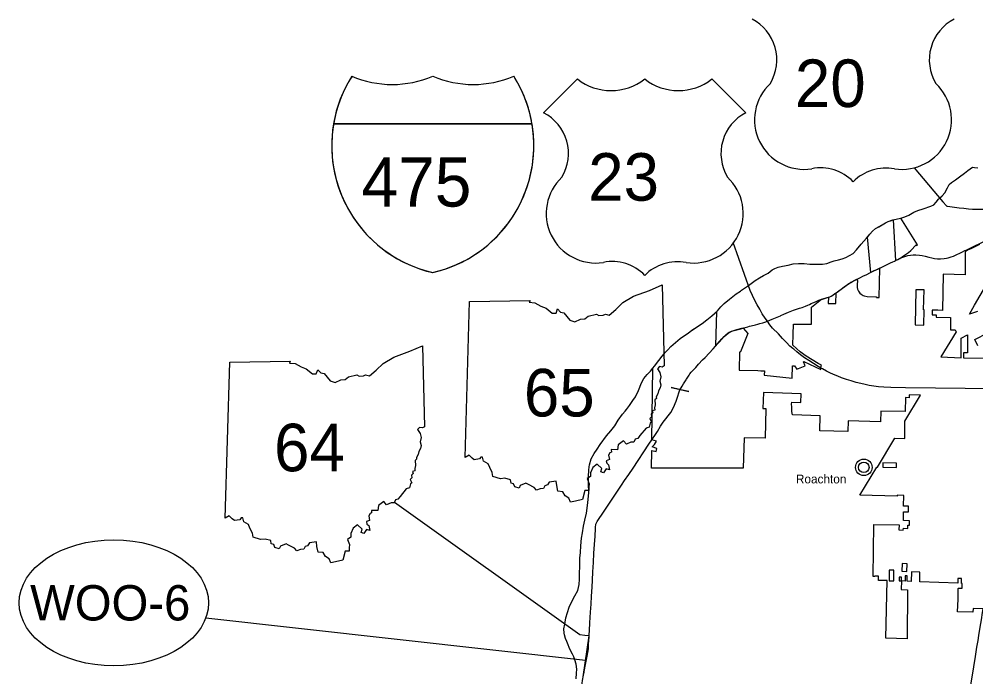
# Model space of a CAD drawing. Extents: x 0 to 851, y 0 to 440.
# Drawn here: x 242.7 to 318.5, y 285 to 337.1 of the extents above; entities that cross this region are included whole.
import ezdxf

# ---------------------------------------------------------------- set-up
doc = ezdxf.new("R2010")
doc.units = 0
for name, color, linetype in [('DV_X_Corp_Line', 7, 'Continuous'), ('GM_X_County', 7, 'Continuous'), ('GM_X_Interstate_Route', 7, 'Continuous'), ('GM_X_State_Route', 7, 'Continuous'), ('GM_X_US_Route', 7, 'Continuous'), ('PV_P_Text', 7, 'Continuous'), ('RD_P_Fence', 7, 'Continuous'), ('SH_Data', 7, 'Continuous')]:
    doc.layers.add(name, color=color, linetype=linetype)

msp = doc.modelspace()

# ---------------------------------------------------------------- linework, layer by layer
at = {"layer": 'DV_X_Corp_Line'}
for points in [[(319.048, 290.414), (318.275, 290.42), (318.257, 290.139), (317.045, 290.161), (317.103, 291.162), (317.111, 292.029), (317.12, 292.049), (317.141, 292.053), (317.415, 292.051), (317.428, 292.418), (317.352, 292.419), (317.357, 292.803), (317.08, 292.81), (317.081, 292.429), (314.051, 292.548), (314.062, 293.308), (313.41, 293.336), (313.376, 292.574), (313.052, 292.589), (313.057, 293.014), (312.902, 293.016), (312.893, 292.596), (312.616, 292.617), (312.592, 291.932), (313.091, 291.917), (313.053, 288.016), (311.365, 288.075), (311.466, 292.647), (310.784, 292.657), (310.797, 292.994), (310.489, 293.006), (310.488, 292.965), (310.356, 292.968), (310.419, 297.085), (312.425, 297.052), (312.413, 296.66), (312.753, 296.64), (312.758, 296.793), (313.108, 296.78), (313.119, 297.038), (313.254, 297.041), (313.257, 297.37), (312.767, 297.395), (312.766, 298.098), (313.154, 298.096), (313.158, 298.537), (312.773, 298.549), (312.795, 299.398), (312.256, 299.407), (312.256, 299.338), (309.321, 299.406), (310.645, 301.632), (310.716, 301.631), (312.076, 303.924), (312.866, 303.916), (312.872, 304.289), (312.887, 305.289), (314.122, 307.353), (313.218, 307.36), (313.209, 307.135), (312.92, 307.148), (312.9, 306.055), (310.973, 306.075), (310.955, 305.238), (308.39, 305.295), (308.367, 304.469), (306.152, 304.505), (306.17, 305.694), (303.972, 305.77), (303.938, 306.056), (303.919, 306.278), (303.915, 306.341), (303.913, 306.414), (303.912, 306.62), (303.913, 306.779), (304.637, 306.758), (304.665, 307.454), (303.929, 307.482), (301.677, 307.542), (301.64, 306.287), (301.875, 306.277), (301.825, 303.923), (300.143, 303.957), (300.078, 301.55), (297.691, 301.546), (297.634, 301.546), (295.605, 301.549), (292.807, 301.55), (292.841, 302.947), (293.173, 302.886), (293.23, 303.108), (292.874, 303.258), (293.057, 303.435), (293.217, 303.684), (292.846, 303.801), (292.924, 309.486), (293.045, 309.641), (293.382, 310.094), (293.657, 310.441), (293.918, 310.754), (294.105, 310.942), (294.345, 311.186), (294.711, 311.518), (295.083, 311.826), (295.421, 312.081), (295.704, 312.266), (295.863, 312.382), (296.44, 312.769), (296.547, 312.84), (296.828, 313.03), (297.207, 313.298), (297.599, 313.616), (297.951, 313.942), (297.893, 311.27), (298.192, 311.57), (298.394, 311.782), (298.576, 311.991), (298.728, 312.13), (298.879, 312.254), (298.985, 312.323), (299.07, 312.37), (299.142, 312.404), (299.254, 312.442), (299.561, 312.525), (299.77, 312.578), (300.073, 312.657), (300.432, 312.216), (299.849, 310.77), (299.794, 310.741), (299.75, 309.319), (301.234, 309.282), (301.475, 309.279), (301.751, 309.275), (301.736, 308.927), (303.958, 308.7), (303.982, 309.669), (304.057, 309.662), (304.129, 309.659), (304.313, 309.401), (304.973, 309.663), (304.853, 309.992), (304.88, 310.011), (306.217, 309.364), (306.234, 309.562), (306.269, 309.717), (306.011, 309.839), (305.074, 310.442), (304.598, 310.784), (304.012, 311.293), (304.033, 312.145), (304.049, 312.956), (305.489, 312.979), (305.489, 314.316), (306.285, 314.937), (306.469, 314.996), (306.581, 315.031), (306.837, 315.11), (306.809, 314.609), (307.418, 314.618), (307.445, 315.464), (307.51, 315.513), (307.827, 315.74), (308.108, 315.944), (308.222, 316.024), (308.449, 316.187), (308.515, 316.229), (308.605, 316.286), (308.688, 316.335), (308.731, 316.358), (308.814, 316.401), (308.923, 316.457), (309.062, 316.526), (309.08, 316.482), (309.089, 316.486), (309.131, 316.402), (309.096, 316.116), (309.102, 315.879), (309.127, 315.747), (309.206, 315.578), (309.318, 315.428), (309.428, 315.337), (309.574, 315.239), (309.644, 315.209), (309.893, 315.154), (310.585, 315.14), (310.632, 315.131), (310.639, 315.072), (310.855, 315.073), (310.886, 317.409), (310.569, 317.258), (310.431, 317.195), (310.183, 317.072), (309.931, 319.871), (310.107, 320.097), (310.308, 320.34), (310.558, 320.546), (310.824, 320.691), (311.35, 321.001), (311.546, 321.106), (311.815, 321.194), (311.916, 321.227), (311.942, 321.232), (312.141, 318.01), (312.491, 318.177), (312.841, 318.426), (313.156, 318.641), (313.353, 318.808), (313.764, 319.245), (313.799, 319.202), (313.882, 319.258), (312.571, 321.371), (312.883, 321.471), (313.193, 321.612), (313.577, 321.836), (313.897, 321.974), (314.317, 322.104), (314.926, 322.312), (315.165, 322.43), (315.355, 322.647), (315.546, 322.887), (315.826, 323.129), (316.047, 323.389), (316.246, 323.766), (316.376, 324.027), (316.579, 324.183), (316.9, 324.415), (317.214, 324.643), (317.595, 324.928), (317.863, 325.157), (318.227, 325.405), (318.398, 325.396), (318.649, 325.36)], [(318.793, 319.294), (318.462, 319.131), (318.146, 318.978), (317.846, 318.825), (317.644, 318.706), (317.642, 316.884), (315.916, 316.93), (315.868, 314.056), (315.494, 314.068), (315.048, 314.075), (315.036, 313.702), (315.35, 313.703), (315.358, 313.52), (316.492, 313.502), (316.492, 312.53), (316.857, 312.524), (316.931, 312.354), (315.734, 310.388), (317.333, 310.295), (317.332, 311.857), (317.831, 312.134), (317.831, 310.704), (317.515, 310.698), (317.515, 310.294), (320.058, 310.283)], [(318.637, 313.963), (318.007, 313.758), (318.396, 314.465), (320.198, 317.551)], [(318.668, 311.238), (318.431, 311.762), (319.452, 312.281)]]:
    msp.add_lwpolyline(points, dxfattribs=at)
for points in [[(313.698, 312.902), (314.378, 312.878), (314.405, 314.099), (314.353, 314.1), (314.406, 315.687), (313.733, 315.696)], [(295.077, 307.794), (295.037, 307.802), (294.381, 307.942)], [(295.766, 307.632), (295.135, 307.766), (295.086, 307.777)], [(312.22, 301.616), (312.223, 301.957), (311.133, 301.976), (311.13, 301.627)], [(312.663, 293.991), (312.642, 293.396), (313.034, 293.367), (313.056, 293.979)], [(311.632, 292.637), (312.016, 292.628), (312.016, 293.48), (311.632, 293.48)], [(312.616, 292.617), (312.615, 292.903), (312.419, 292.903), (312.415, 292.624)]]:
    msp.add_lwpolyline(points, close=True, dxfattribs=at)
for radius in [0.658, 0.417]:
    msp.add_circle((309.626, 301.62), radius, dxfattribs=at)
at = {"layer": 'GM_X_County'}
msp.add_lwpolyline([(286.857, 284.869), (286.885, 285.309), (286.901, 285.632), (286.84, 286.009), (286.748, 286.351), (286.652, 286.601), (286.548, 286.808), (286.385, 287.103), (286.288, 287.33), (286.208, 287.56), (286.098, 287.824), (286.005, 288.051), (285.912, 288.345), (285.897, 288.482), (285.861, 288.816), (285.949, 289.184), (286.039, 289.691), (286.148, 290.116), (286.293, 290.525), (286.533, 291.04), (286.736, 291.444), (286.975, 291.855), (287.091, 292.324), (287.103, 292.764), (287.118, 293.211), (287.138, 293.782), (287.148, 294.414), (287.197, 294.881), (287.217, 295.405), (287.257, 296.003), (287.336, 296.425), (287.425, 296.945), (287.538, 297.428), (287.659, 297.998), (287.752, 298.592), (287.788, 299.069), (287.838, 299.63), (287.816, 300.309), (287.829, 300.903), (287.838, 301.384), (287.873, 301.661), (287.893, 301.82), (288.029, 302.283), (288.282, 302.72), (288.504, 303.05), (288.759, 303.434), (289.256, 304.104), (289.579, 304.51), (289.902, 304.914), (290.172, 305.351), (290.526, 305.831), (290.716, 306.066), (290.838, 306.217), (291.073, 306.53), (291.339, 306.914), (291.54, 307.221), (291.783, 307.709), (292.025, 308.311), (292.203, 308.649), (292.471, 308.972), (292.742, 309.254), (292.924, 309.486), (293.045, 309.641), (293.382, 310.094), (293.657, 310.441), (293.918, 310.754), (294.105, 310.942), (294.345, 311.186), (294.711, 311.518), (295.083, 311.826), (295.421, 312.081), (295.704, 312.266), (295.863, 312.382), (296.083, 312.541), (296.44, 312.769), (296.828, 313.03), (297.207, 313.298), (297.599, 313.616), (298.029, 314.015), (298.304, 314.341), (298.558, 314.6), (298.988, 314.959), (299.512, 315.366), (299.854, 315.595), (299.947, 315.657), (300.497, 316.023), (301.031, 316.428), (301.375, 316.636), (301.685, 316.824), (302.039, 317.011), (302.364, 317.273), (302.58, 317.392), (302.855, 317.476), (303.191, 317.553), (303.628, 317.649), (304.028, 317.759), (304.453, 317.784), (304.909, 317.769), (305.36, 317.73), (305.836, 317.722), (306.342, 317.716), (306.687, 317.769), (307.041, 317.896), (307.289, 317.984), (307.629, 318.071), (307.921, 318.135), (308.197, 318.253), (308.787, 318.566), (309.051, 318.859), (309.415, 319.305), (309.852, 319.771), (310.107, 320.097), (310.308, 320.34), (310.558, 320.546), (310.902, 320.734), (311.35, 321.001), (311.546, 321.106), (311.916, 321.227), (312.571, 321.37), (312.883, 321.471), (313.193, 321.612), (313.577, 321.836), (313.897, 321.974), (314.317, 322.104), (314.926, 322.312), (315.165, 322.43), (315.355, 322.647), (315.546, 322.887), (315.631, 322.961), (315.826, 323.129), (316.047, 323.389), (316.246, 323.766), (316.376, 324.027), (316.579, 324.183), (316.9, 324.415), (317.214, 324.643), (317.595, 324.928), (317.863, 325.157), (318.227, 325.405), (318.398, 325.396), (318.649, 325.36)], dxfattribs=at)
at = {"layer": 'GM_X_Interstate_Route'}
for points in [[(301.992, 313.205), (301.816, 313.453), (301.587, 313.791), (301.383, 314.151), (301.184, 314.507), (300.973, 314.893), (300.804, 315.228), (300.639, 315.625), (299.276, 319.435)], [(306.144, 309.54), (306.135, 309.545), (306.02, 309.609), (305.629, 309.847), (305.262, 310.081), (304.937, 310.294), (304.617, 310.524), (304.319, 310.767), (304.072, 310.976), (304.002, 311.038), (303.778, 311.236), (303.505, 311.502), (303.199, 311.819), (302.857, 312.204), (302.396, 312.638), (302.179, 312.914), (301.992, 313.205)], [(321.825, 307.801), (320.133, 307.84), (320.02, 307.851), (312.929, 307.924), (311.76, 307.955), (311.222, 307.978), (310.795, 308.013), (310.42, 308.043), (310.05, 308.113), (309.736, 308.178), (309.383, 308.257), (309.023, 308.354), (308.624, 308.464), (308.248, 308.584), (307.869, 308.711), (307.566, 308.836), (307.238, 308.986), (306.945, 309.115), (306.66, 309.253), (306.342, 309.43), (306.144, 309.54)]]:
    msp.add_lwpolyline(points, dxfattribs=at)
at = {"layer": 'GM_X_State_Route'}
for points in [[(317.622, 318.794), (317.676, 318.819), (318.368, 319.149), (318.87, 319.384), (320.312, 320.085)], [(312.045, 317.966), (312.138, 318.008), (312.312, 318.088), (312.461, 318.166), (312.573, 318.213), (312.704, 318.273), (312.866, 318.332), (313.109, 318.402), (313.323, 318.442), (313.533, 318.457), (313.741, 318.47)], [(313.741, 318.47), (314.046, 318.441), (314.251, 318.404), (314.489, 318.355), (314.773, 318.285), (315.014, 318.23), (315.237, 318.184), (315.473, 318.154), (315.705, 318.151), (315.989, 318.169), (316.17, 318.199), (316.3, 318.224), (316.38, 318.245), (316.538, 318.297), (316.719, 318.364), (316.997, 318.49), (317.221, 318.593), (317.442, 318.708), (317.622, 318.794)], [(310.834, 317.39), (310.886, 317.414), (311.318, 317.615), (311.75, 317.822), (311.927, 317.912), (312.045, 317.966)], [(308.89, 316.438), (309.089, 316.54), (309.361, 316.674), (309.542, 316.761), (309.874, 316.917), (310.101, 317.035)], [(310.101, 317.035), (310.164, 317.068), (310.431, 317.195), (310.564, 317.258), (310.781, 317.366), (310.834, 317.39)], [(307.66, 315.611), (307.827, 315.73), (308.125, 315.956), (308.236, 316.041), (308.463, 316.197), (308.584, 316.269)], [(308.584, 316.269), (308.589, 316.272), (308.734, 316.359), (308.89, 316.438)], [(306.929, 315.138), (306.94, 315.142), (307.048, 315.193), (307.184, 315.275), (307.337, 315.386), (307.446, 315.46)], [(307.446, 315.46), (307.546, 315.529), (307.66, 315.611)], [(304.066, 314.086), (304.066, 314.086), (304.212, 314.128), (304.545, 314.229), (304.745, 314.293), (304.866, 314.332), (305.011, 314.39), (305.199, 314.478), (305.331, 314.536), (305.445, 314.601), (305.577, 314.66), (305.812, 314.747), (306.065, 314.862), (306.231, 314.921), (306.332, 314.954), (306.345, 314.957)], [(306.345, 314.957), (306.73, 315.073), (306.929, 315.138)], [(303.033, 313.637), (303.06, 313.649), (303.286, 313.748), (303.66, 313.911), (304.066, 314.086)], [(300.449, 312.769), (300.566, 312.8), (300.71, 312.838), (301.046, 312.92), (301.231, 312.965), (301.385, 313.013), (301.618, 313.071), (301.797, 313.134), (301.992, 313.205)], [(301.992, 313.205), (302.373, 313.355), (302.764, 313.518), (303.033, 313.637)], [(297.702, 311.025), (297.88, 311.213), (298.19, 311.591), (298.377, 311.793), (298.568, 311.999), (298.717, 312.144), (298.862, 312.263), (298.971, 312.335), (299.092, 312.393), (299.25, 312.448), (299.559, 312.534), (299.955, 312.642), (299.992, 312.651)], [(299.992, 312.651), (300.338, 312.74), (300.449, 312.769)], [(295.576, 308.596), (295.793, 308.932), (295.852, 309.033), (295.963, 309.159), (296.141, 309.353), (296.326, 309.545), (296.544, 309.784), (296.86, 310.141), (297.051, 310.335), (297.702, 311.025)], [(295.108, 307.851), (295.161, 307.928), (295.233, 308.061), (295.35, 308.241), (295.555, 308.563), (295.576, 308.596)], [(295, 307.611), (295.029, 307.685), (295.093, 307.828), (295.108, 307.851)], [(292.887, 303.869), (293.066, 304.141), (293.279, 304.469), (293.535, 304.87), (293.729, 305.19), (294.336, 305.962), (294.545, 306.357), (294.761, 306.854), (294.901, 307.274), (294.965, 307.527), (295, 307.611)], [(291.373, 301.542), (292.611, 303.461), (292.843, 303.804), (292.887, 303.869)], [(290.428, 300.194), (290.684, 300.577), (291.006, 301.065), (291.373, 301.542)], [(287.875, 288.263), (287.878, 288.342), (287.895, 288.675), (287.934, 289.296), (287.988, 290.138), (288.034, 290.772), (288.074, 291.406), (288.112, 292.118), (288.147, 292.681), (288.174, 293.332), (288.219, 294.087), (288.258, 294.825), (288.301, 295.506), (288.345, 296.17), (288.378, 296.761), (288.38, 296.919), (288.392, 297.039), (288.41, 297.126), (288.445, 297.22), (288.5, 297.316), (288.606, 297.483), (288.948, 297.982), (289.113, 298.234), (290.428, 300.194)], [(287.875, 288.263), (287.531, 288.299), (287.14, 288.346), (272.451, 298.841)], [(317.965, 283.565), (318.056, 284.051), (318.21, 284.99), (318.342, 285.798), (318.465, 286.621), (318.58, 287.355), (318.674, 287.903), (318.734, 288.303), (318.84, 288.954), (318.934, 289.522), (319.023, 290.102), (319.081, 290.432)], [(287.473, 285.386), (287.473, 285.387), (287.486, 285.448), (287.593, 285.994), (287.721, 286.647), (287.802, 287.082), (287.818, 287.246), (287.829, 287.488), (287.857, 287.968), (287.865, 288.087)], [(287.865, 288.087), (287.865, 288.089), (287.875, 288.263)], [(287.006, 283.612), (287.04, 283.689), (287.08, 283.782), (287.177, 284.009), (287.268, 284.216), (287.3, 284.319), (287.326, 284.5), (287.343, 284.715), (287.362, 284.852), (287.395, 285.02), (287.473, 285.386)]]:
    msp.add_lwpolyline(points, dxfattribs=at)
at = {"layer": 'GM_X_US_Route'}
msp.add_lwpolyline([(313.604, 325.357), (315.888, 322.657), (316.165, 322.35), (316.191, 322.327), (316.205, 322.325), (316.248, 322.319), (316.621, 322.266), (317.175, 322.2), (317.559, 322.157), (317.91, 322.118), (318.23, 322.09), (318.353, 322.085), (318.511, 322.079), (318.986, 322.078), (319.414, 322.082)], dxfattribs=at)
at = {"layer": 'PV_P_Text'}
for p, q in [((286.951, 332.401), (284.272, 329.722)), ((286.951, 332.401), (284.272, 329.722)), ((300.279, 329.722), (297.599, 332.401)), ((300.279, 329.722), (297.599, 332.401)), ((267.634, 328.846), (283.349, 328.846)), ((283.349, 328.846), (267.634, 328.846)), ((283.349, 328.846), (267.634, 328.846)), ((278.046, 302.398), (278.392, 314.771)), ((259.06, 297.584), (259.407, 309.957)), ((259.06, 297.584), (259.407, 309.957))]:
    msp.add_line(p, q, dxfattribs=at)
for points in [[(278.392, 314.771), (283.193, 314.851), (283.118, 314.701), (283.571, 314.67), (284.052, 314.406), (284.459, 314.239), (284.956, 313.846), (285.254, 313.85), (285.38, 314.173), (285.608, 313.924), (285.879, 313.879), (286.347, 313.287), (286.733, 313.159), (287.196, 313.362), (287.542, 313.395), (287.794, 313.596), (288.453, 313.767), (288.637, 313.664), (288.986, 313.685), (289.161, 313.761), (289.465, 313.693), (290.001, 314.143), (290.552, 314.674), (291.4, 315.174), (292.666, 315.648), (293.668, 316.072), (293.812, 309.652)], [(259.407, 309.957), (264.207, 310.038), (264.132, 309.888), (264.585, 309.856), (265.066, 309.592), (265.473, 309.425), (265.971, 309.032), (266.269, 309.036), (266.395, 309.359), (266.623, 309.11), (266.893, 309.065), (267.361, 308.473), (267.748, 308.345), (268.21, 308.548), (268.556, 308.581), (268.809, 308.782), (269.468, 308.953), (269.651, 308.851), (270, 308.871), (270.176, 308.947), (270.48, 308.88), (271.015, 309.329), (271.566, 309.86), (272.414, 310.36), (273.681, 310.834), (274.682, 311.259), (274.827, 304.838)], [(259.407, 309.957), (264.207, 310.038), (264.132, 309.888), (264.585, 309.856), (265.066, 309.592), (265.473, 309.425), (265.971, 309.032), (266.269, 309.036), (266.395, 309.359), (266.623, 309.11), (266.893, 309.065), (267.361, 308.473), (267.748, 308.345), (268.21, 308.548), (268.556, 308.581), (268.809, 308.782), (269.468, 308.953), (269.651, 308.851), (270, 308.871), (270.176, 308.947), (270.48, 308.88), (271.015, 309.329), (271.566, 309.86), (272.414, 310.36), (273.681, 310.834), (274.682, 311.259), (274.827, 304.838)], [(293.812, 309.652), (293.664, 309.562), (293.434, 309.604), (293.28, 309.424), (293.471, 309.124), (293.562, 308.806), (293.481, 308.456), (293.56, 308.168), (293.507, 307.926), (293.362, 307.686), (293.312, 307.457), (293.189, 307.215), (293.2, 307.08), (293.082, 306.973), (293.103, 306.571), (293.044, 306.349), (293.065, 306.157), (292.875, 306.107), (292.918, 305.948), (292.797, 305.826), (292.823, 305.615), (292.686, 305.48), (292.819, 305.211), (292.712, 305.125), (292.624, 304.798), (292.38, 304.731), (291.891, 304.132), (291.719, 303.906), (291.526, 303.849), (291.419, 303.617), (291.181, 303.616), (290.82, 303.455), (290.587, 303.732), (290.179, 303.398), (290.132, 303.012), (289.615, 303.025), (289.635, 302.83), (289.52, 302.773), (289.415, 302.577), (289.476, 302.23), (289.234, 302.142), (289.264, 301.94), (289.418, 301.817), (289.487, 301.431), (289.23, 301.51), (289.02, 301.185), (288.803, 301.261), (288.874, 301.536), (288.509, 301.867), (288.162, 301.602), (287.982, 301.179), (287.98, 300.894), (287.722, 300.722), (287.888, 300.319), (287.857, 300.042), (287.862, 299.779), (287.54, 299.788), (287.345, 299.078)], [(274.827, 304.838), (274.679, 304.748), (274.449, 304.79), (274.294, 304.61), (274.486, 304.31), (274.576, 303.992), (274.496, 303.642), (274.575, 303.354), (274.521, 303.112), (274.377, 302.872), (274.326, 302.643), (274.204, 302.401), (274.214, 302.266), (274.097, 302.159), (274.118, 301.758), (274.059, 301.535), (274.079, 301.343), (273.889, 301.293), (273.933, 301.134), (273.812, 301.012), (273.838, 300.801), (273.7, 300.667), (273.834, 300.397), (273.727, 300.312), (273.638, 299.984), (273.394, 299.918), (272.906, 299.318), (272.734, 299.092), (272.54, 299.036), (272.433, 298.803), (272.195, 298.802), (271.835, 298.641), (271.602, 298.918), (271.193, 298.584), (271.146, 298.198), (270.63, 298.211), (270.65, 298.016), (270.535, 297.959), (270.429, 297.764), (270.49, 297.416), (270.249, 297.328), (270.278, 297.126), (270.433, 297.003), (270.502, 296.618), (270.245, 296.696), (270.034, 296.371), (269.818, 296.447), (269.889, 296.722), (269.523, 297.053), (269.177, 296.788), (268.997, 296.365), (268.994, 296.08), (268.737, 295.908), (268.902, 295.505), (268.872, 295.228), (268.877, 294.965), (268.555, 294.975), (268.359, 294.264)], [(274.827, 304.838), (274.679, 304.748), (274.449, 304.79), (274.294, 304.61), (274.486, 304.31), (274.576, 303.992), (274.496, 303.642), (274.575, 303.354), (274.521, 303.112), (274.377, 302.872), (274.326, 302.643), (274.204, 302.401), (274.214, 302.266), (274.097, 302.159), (274.118, 301.758), (274.059, 301.535), (274.079, 301.343), (273.889, 301.293), (273.933, 301.134), (273.812, 301.012), (273.838, 300.801), (273.7, 300.667), (273.834, 300.397), (273.727, 300.312), (273.638, 299.984), (273.394, 299.918), (272.906, 299.318), (272.734, 299.092), (272.54, 299.036), (272.433, 298.803), (272.195, 298.802), (271.835, 298.641), (271.602, 298.918), (271.193, 298.584), (271.146, 298.198), (270.63, 298.211), (270.65, 298.016), (270.535, 297.959), (270.429, 297.764), (270.49, 297.416), (270.249, 297.328), (270.278, 297.126), (270.433, 297.003), (270.502, 296.618), (270.245, 296.696), (270.034, 296.371), (269.818, 296.447), (269.889, 296.722), (269.523, 297.053), (269.177, 296.788), (268.997, 296.365), (268.994, 296.08), (268.737, 295.908), (268.902, 295.505), (268.872, 295.228), (268.877, 294.965), (268.555, 294.975), (268.359, 294.264)], [(287.345, 299.078), (286.785, 298.942), (286.396, 298.861), (286.259, 299.184), (285.981, 299.354), (285.8, 299.679), (285.4, 299.723), (285.306, 300.169), (285.261, 300.531), (284.715, 300.442), (284.565, 300.22), (284.372, 300.161), (284.259, 299.938), (283.995, 299.919), (283.712, 299.814), (283.527, 300.033), (283.062, 300.252), (282.854, 300.366), (282.418, 300.19), (282.324, 299.981), (281.977, 300.073), (281.896, 300.305), (281.686, 300.375), (281.639, 300.622), (281.19, 300.753), (280.847, 300.701), (280.241, 300.899), (280.204, 301.223), (279.997, 301.618), (279.89, 301.893), (279.507, 302.102), (279.429, 302.428), (279.306, 302.419), (279.194, 302.286), (278.769, 302.225), (278.599, 302.359), (278.361, 302.586), (278.046, 302.398)], [(268.359, 294.264), (267.799, 294.128), (267.41, 294.047), (267.273, 294.37), (266.995, 294.54), (266.814, 294.865), (266.415, 294.909), (266.32, 295.355), (266.275, 295.717), (265.73, 295.628), (265.58, 295.406), (265.386, 295.347), (265.274, 295.124), (265.01, 295.105), (264.726, 295), (264.541, 295.219), (264.077, 295.438), (263.869, 295.552), (263.432, 295.376), (263.339, 295.167), (262.992, 295.259), (262.91, 295.492), (262.7, 295.561), (262.654, 295.808), (262.205, 295.939), (261.861, 295.887), (261.255, 296.085), (261.218, 296.409), (261.012, 296.804), (260.904, 297.079), (260.521, 297.288), (260.443, 297.614), (260.321, 297.605), (260.209, 297.472), (259.783, 297.412), (259.613, 297.545), (259.375, 297.773), (259.06, 297.584)], [(268.359, 294.264), (267.799, 294.128), (267.41, 294.047), (267.273, 294.37), (266.995, 294.54), (266.814, 294.865), (266.415, 294.909), (266.32, 295.355), (266.275, 295.717), (265.73, 295.628), (265.58, 295.406), (265.386, 295.347), (265.274, 295.124), (265.01, 295.105), (264.726, 295), (264.541, 295.219), (264.077, 295.438), (263.869, 295.552), (263.432, 295.376), (263.339, 295.167), (262.992, 295.259), (262.91, 295.492), (262.7, 295.561), (262.654, 295.808), (262.205, 295.939), (261.861, 295.887), (261.255, 296.085), (261.218, 296.409), (261.012, 296.804), (260.904, 297.079), (260.521, 297.288), (260.443, 297.614), (260.321, 297.605), (260.209, 297.472), (259.783, 297.412), (259.613, 297.545), (259.375, 297.773), (259.06, 297.584)]]:
    msp.add_lwpolyline(points, dxfattribs=at)
for centre, radius, start, end in [((299.098, 333.912), 3.642, 329.11751, 62.61081), ((299.098, 333.912), 3.642, 329.11751, 62.61081), ((318.455, 333.912), 3.642, 117.38919, 210.88249), ((318.455, 333.912), 3.642, 117.38919, 210.88249), ((277.816, 327.116), 10.328, 147.82161, 256.99413), ((277.17, 327.295), 9.662, 146.65397, 170.75899), ((272.283, 340.207), 8.241, 247.08482, 292.91053), ((272.283, 340.207), 8.241, 247.08482, 292.91053), ((273.167, 327.116), 10.328, 283.00654, 32.17868), ((278.7, 340.209), 8.243, 247.09162, 292.90836), ((278.7, 340.209), 8.243, 247.09162, 292.90836), ((273.167, 327.116), 10.328, 9.64753, 32.17902), ((289.613, 335.785), 4.306, 231.81301, 308.18697), ((289.613, 335.785), 4.306, 231.81301, 308.18697), ((294.937, 335.785), 4.306, 231.81301, 308.18697), ((294.937, 335.785), 4.306, 231.81301, 308.18697), ((304.904, 329.169), 3.93, 133.00455, 278.72816), ((304.904, 329.169), 3.93, 133.00455, 278.72816), ((312.649, 329.169), 3.93, 261.27184, 46.99545), ((312.649, 329.169), 3.93, 261.27184, 46.99545), ((282.597, 326.488), 3.642, 329.11751, 62.61081), ((282.597, 326.488), 3.642, 329.11751, 62.61081), ((301.954, 326.488), 3.642, 117.38919, 210.88249), ((301.954, 326.488), 3.642, 117.38919, 210.88249), ((277.815, 327.115), 10.328, 170.35136, 256.9967), ((273.188, 327.111), 10.308, 282.76665, 9.68983), ((306.223, 321.845), 3.515, 43.41772, 101.87423), ((306.223, 321.845), 3.515, 43.41772, 101.87423), ((311.403, 321.611), 3.731, 79.96126, 134.74679), ((311.403, 321.611), 3.731, 79.96126, 134.74679), ((288.402, 321.745), 3.93, 133.00455, 278.72816), ((288.402, 321.745), 3.93, 133.00455, 278.72816), ((296.148, 321.745), 3.93, 261.27184, 46.99545), ((296.148, 321.745), 3.93, 261.27184, 46.99545), ((289.722, 314.421), 3.515, 43.41772, 101.87423), ((289.722, 314.421), 3.515, 43.41772, 101.87423), ((294.901, 314.187), 3.731, 79.96126, 134.74679), ((294.901, 314.187), 3.731, 79.96126, 134.74679)]:
    msp.add_arc(centre, radius, start, end, dxfattribs=at)
at = {"layer": 'RD_P_Fence'}
msp.add_lwpolyline([(287.395, 285.02), (287.395, 285.02), (287.395, 285.02), (287.395, 285.02), (287.875, 288.263)], dxfattribs=at)
at = {"layer": 'SH_Data'}
msp.add_line((257.515, 289.685), (287.589, 286.329), dxfattribs=at)
msp.add_ellipse((250.233, 290.882), major_axis=(7.5, 0), ratio=0.666667, dxfattribs=at)

# ---------------------------------------------------------------- texts
at = {"layer": 'DV_X_Corp_Line'}
msp.add_text('Roachton', height=0.6979, rotation=0.00001, dxfattribs=at).set_placement((304.249, 300.347))
at = {"layer": 'PV_P_Text'}
for s, height, p in [('20', 3.7688, (304.17, 330.178)), ('23', 3.7688, (287.802, 322.754)), ('475', 3.9007, (269.846, 322.287)), ('65', 3.7688, (282.706, 305.654)), ('64', 3.7688, (262.921, 301.306))]:
    msp.add_text(s, height=height, dxfattribs=at).set_placement(p)
at = {"layer": 'SH_Data'}
msp.add_text('WOO-6', height=2.8, dxfattribs=at).set_placement((243.604, 289.482))

doc.saveas('drawing.dxf')
